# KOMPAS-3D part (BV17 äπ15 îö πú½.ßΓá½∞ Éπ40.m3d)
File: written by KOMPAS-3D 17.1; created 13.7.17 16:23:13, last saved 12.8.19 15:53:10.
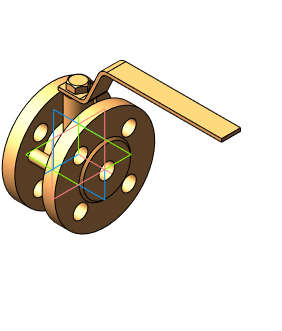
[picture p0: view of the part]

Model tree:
1. Операция без истории:2  (labels: Сталь 20  ГОСТ 1050-88)

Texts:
  DISO1
  DISO2
  BV17 Ду10 ФФ Ру40 угл. сталь
  BV17 Ду15 ФФ Ру40 угл. сталь
  BV17 Ду20 ФФ Ру40 угл. сталь
  BV17 Ду25 ФФ Ру40 угл. сталь
  BV17 Ду32 ФФ Ру40 угл. сталь
  BV17 Ду40 ФФ Ру40 угл. сталь
  BV17 Ду50 ФФ Ру40 угл. сталь
  BV17 Ду65 ФФ Ру40 угл. сталь
  BV17 Ду80 ФФ Ру40 угл. сталь
  BV17 Ду100 ФФ Ру40 угл. сталь
  BV17 Ду125 ФФ Ру40 угл. сталь
  BV17 Ду150 ФФ Ру40 угл. сталь
  BV17 Ду200 ФФ Ру40 угл. сталь
  BV17 Ду250 ФФ Ру40 угл. сталь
